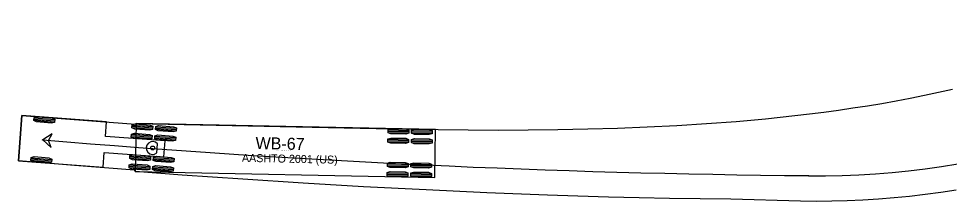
# Model space of a CAD drawing. Extents: x 1639988 to 1641860, y 841974 to 844187.
# Drawn here: x 1640630.6 to 1640795.3, y 842661.9 to 842694.2 of the extents above; entities that cross this region are included whole.
import ezdxf

# ---------------------------------------------------------------- set-up
doc = ezdxf.new("R2010")
doc.units = 0
doc.layers.add('Scratch_Level_1', color=7, linetype='Continuous')

msp = doc.modelspace()

# ---------------------------------------------------------------- linework, layer by layer
at = {"layer": 'Scratch_Level_1'}
for p, q in [((1640631.18, 842677.08), (1640630.59, 842669.1)), ((1640646.14, 842675.98), (1640631.18, 842677.08)), ((1640633.29, 842676.25), (1640636.95, 842675.95)), ((1640633.31, 842676.48), (1640636.97, 842676.17)), ((1640633.33, 842676.71), (1640636.98, 842676.4)), ((1640645.95, 842673.42), (1640646.14, 842675.98)), ((1640651.41, 842675.68), (1640651.24, 842667.19)), ((1640704.4, 842674.61), (1640651.41, 842675.68)), ((1640650.66, 842674.96), (1640654.32, 842674.7)), ((1640650.68, 842675.19), (1640654.33, 842674.93)), ((1640650.69, 842675.42), (1640654.35, 842675.15)), ((1640654.81, 842674.66), (1640658.47, 842674.39)), ((1640654.83, 842674.89), (1640658.49, 842674.62)), ((1640654.85, 842675.12), (1640658.5, 842674.85)), ((1640695.97, 842674.33), (1640699.64, 842674.25)), ((1640695.97, 842674.1), (1640699.64, 842674.02)), ((1640695.98, 842674.56), (1640699.65, 842674.48)), ((1640700.14, 842674.24), (1640703.81, 842674.17)), ((1640700.14, 842674.01), (1640703.8, 842673.94)), ((1640700.15, 842674.47), (1640703.81, 842674.4)), ((1640704.23, 842666.12), (1640704.4, 842674.61)), ((1640656.51, 842672.65), (1640645.95, 842673.42)), ((1640650.54, 842673.32), (1640654.2, 842673.05)), ((1640650.56, 842673.55), (1640654.21, 842673.28)), ((1640650.57, 842673.78), (1640654.23, 842673.51)), ((1640654.69, 842673.01), (1640658.35, 842672.75)), ((1640654.71, 842673.24), (1640658.37, 842672.98)), ((1640654.73, 842673.47), (1640658.38, 842673.2)), ((1640656.3, 842669.79), (1640656.51, 842672.65)), ((1640695.94, 842672.68), (1640699.61, 842672.6)), ((1640695.94, 842672.45), (1640699.6, 842672.37)), ((1640695.95, 842672.91), (1640699.61, 842672.83)), ((1640700.1, 842672.36), (1640703.77, 842672.29)), ((1640700.11, 842672.82), (1640703.78, 842672.75)), ((1640700.11, 842672.59), (1640703.77, 842672.52)), ((1640645.55, 842668), (1640645.74, 842670.56)), ((1640645.74, 842670.56), (1640656.3, 842669.79)), ((1640655.07, 842670.51), (1640655.19, 842672.12)), ((1640630.59, 842669.1), (1640645.55, 842668)), ((1640630.59, 842669.1), (1640630.59, 842669.1)), ((1640632.77, 842669.19), (1640636.42, 842668.88)), ((1640632.79, 842669.42), (1640636.44, 842669.11)), ((1640632.8, 842669.65), (1640636.46, 842669.34)), ((1640650.26, 842669.55), (1640653.92, 842669.28)), ((1640650.28, 842669.77), (1640653.94, 842669.51)), ((1640650.3, 842670), (1640653.95, 842669.74)), ((1640654.42, 842669.24), (1640658.08, 842668.97)), ((1640654.44, 842669.47), (1640658.09, 842669.2)), ((1640654.45, 842669.7), (1640658.11, 842669.43)), ((1640650.14, 842667.9), (1640653.8, 842667.63)), ((1640650.16, 842668.13), (1640653.82, 842667.86)), ((1640650.18, 842668.36), (1640653.83, 842668.09)), ((1640654.3, 842667.6), (1640657.96, 842667.33)), ((1640654.31, 842667.82), (1640657.97, 842667.56)), ((1640654.33, 842668.05), (1640657.99, 842667.79)), ((1640695.85, 842668.17), (1640699.52, 842668.09)), ((1640695.86, 842668.62), (1640699.53, 842668.55)), ((1640695.86, 842668.39), (1640699.52, 842668.32)), ((1640700.02, 842668.31), (1640703.69, 842668.24)), ((1640700.02, 842668.08), (1640703.68, 842668.01)), ((1640700.03, 842668.54), (1640703.69, 842668.47)), ((1640651.24, 842667.19), (1640704.23, 842666.12)), ((1640651.24, 842667.19), (1640651.24, 842667.19)), ((1640695.82, 842666.74), (1640699.49, 842666.67)), ((1640695.82, 842666.52), (1640699.48, 842666.44)), ((1640695.83, 842666.97), (1640699.49, 842666.9)), ((1640699.98, 842666.43), (1640703.65, 842666.36)), ((1640699.99, 842666.89), (1640703.66, 842666.82)), ((1640699.99, 842666.66), (1640703.65, 842666.59))]:
    msp.add_line(p, q, dxfattribs=at)
for points in [[(1640796.53, 842663.91), (1640793.78, 842663.49), (1640791.04, 842663.12), (1640788.29, 842662.81), (1640785.53, 842662.54), (1640782.78, 842662.32), (1640780.02, 842662.15), (1640777.26, 842662.03), (1640774.51, 842661.95), (1640771.75, 842661.93), (1640769, 842661.96), (1640756.66, 842662.32), (1640751.23, 842662.35), (1640745.8, 842662.43), (1640740.39, 842662.53), (1640734.98, 842662.67), (1640729.59, 842662.83), (1640724.2, 842663.02), (1640713.44, 842663.45), (1640702.71, 842663.95), (1640691.66, 842664.52), (1640680.97, 842665.15), (1640670.27, 842665.83), (1640659.55, 842666.57), (1640651.24, 842667.19), (1640651.12, 842667.44), (1640640.51, 842668.27), (1640630.59, 842669.1), (1640631.18, 842677.08), (1640651.26, 842675.59), (1640651.41, 842675.68), (1640693.88, 842674.83), (1640704.87, 842674.62), (1640710.16, 842674.56), (1640715.46, 842674.54), (1640720.75, 842674.56), (1640726.03, 842674.62), (1640731.31, 842674.72), (1640736.59, 842674.88), (1640741.85, 842675.08), (1640747.1, 842675.35), (1640752.34, 842675.67), (1640757.57, 842676.07), (1640762.78, 842676.53), (1640765.37, 842676.8), (1640767.96, 842677.08), (1640770.55, 842677.38), (1640773.13, 842677.71), (1640775.69, 842678.06), (1640778.25, 842678.43), (1640780.81, 842678.83), (1640783.35, 842679.25), (1640785.88, 842679.7), (1640788.4, 842680.18), (1640790.9, 842680.68), (1640793.39, 842681.22), (1640795.87, 842681.78)], [(1640634.88, 842672.8), (1640636.35, 842671.45), (1640635.87, 842672.71), (1640636.56, 842673.88), (1640634.88, 842672.8)]]:
    msp.add_lwpolyline(points, dxfattribs=at)
for points in [[(1640633.29, 842676.2), (1640633.34, 842676.77), (1640633.86, 842676.89), (1640636.49, 842676.67), (1640636.99, 842676.46), (1640636.94, 842675.89), (1640636.42, 842675.76), (1640633.78, 842675.98)], [(1640650.65, 842674.91), (1640650.7, 842675.48), (1640651.22, 842675.61), (1640653.85, 842675.42), (1640654.35, 842675.21), (1640654.31, 842674.64), (1640653.79, 842674.51), (1640651.15, 842674.7)], [(1640634.88, 842672.8), (1640636.35, 842671.45), (1640635.87, 842672.71), (1640636.56, 842673.88)], [(1640650.53, 842673.26), (1640650.58, 842673.83), (1640651.1, 842673.97), (1640653.73, 842673.77), (1640654.23, 842673.56), (1640654.19, 842672.99), (1640653.67, 842672.86), (1640651.03, 842673.05)], [(1640654.81, 842674.6), (1640654.85, 842675.17), (1640655.38, 842675.31), (1640658.01, 842675.12), (1640658.51, 842674.91), (1640658.47, 842674.34), (1640657.94, 842674.2), (1640655.31, 842674.39)], [(1640695.97, 842674.04), (1640695.98, 842674.61), (1640696.5, 842674.77), (1640699.14, 842674.72), (1640699.65, 842674.54), (1640699.64, 842673.97), (1640699.12, 842673.8), (1640696.48, 842673.86)], [(1640700.13, 842673.96), (1640700.15, 842674.53), (1640700.66, 842674.69), (1640703.3, 842674.64), (1640703.81, 842674.45), (1640703.8, 842673.88), (1640703.28, 842673.72), (1640700.64, 842673.77)], [(1640654.69, 842672.96), (1640654.73, 842673.53), (1640655.26, 842673.66), (1640657.89, 842673.47), (1640658.39, 842673.26), (1640658.35, 842672.69), (1640657.82, 842672.56), (1640655.19, 842672.75)], [(1640695.94, 842672.39), (1640695.95, 842672.96), (1640696.46, 842673.12), (1640699.1, 842673.07), (1640699.61, 842672.89), (1640699.6, 842672.32), (1640699.09, 842672.16), (1640696.45, 842672.21)], [(1640700.1, 842672.31), (1640700.11, 842672.88), (1640700.63, 842673.04), (1640703.27, 842672.99), (1640703.78, 842672.8), (1640703.77, 842672.23), (1640703.25, 842672.07), (1640700.61, 842672.12)], [(1640632.76, 842669.13), (1640632.81, 842669.7), (1640633.34, 842669.83), (1640635.97, 842669.61), (1640636.46, 842669.4), (1640636.42, 842668.83), (1640635.89, 842668.7), (1640633.26, 842668.92)], [(1640650.26, 842669.49), (1640650.3, 842670.06), (1640650.82, 842670.19), (1640653.46, 842670), (1640653.96, 842669.79), (1640653.92, 842669.22), (1640653.39, 842669.09), (1640650.76, 842669.28)], [(1640654.41, 842669.18), (1640654.46, 842669.76), (1640654.98, 842669.89), (1640657.61, 842669.7), (1640658.11, 842669.49), (1640658.07, 842668.92), (1640657.55, 842668.78), (1640654.91, 842668.98)], [(1640650.14, 842667.84), (1640650.18, 842668.41), (1640650.7, 842668.55), (1640653.34, 842668.36), (1640653.84, 842668.15), (1640653.8, 842667.58), (1640653.27, 842667.44), (1640650.64, 842667.63)], [(1640654.29, 842667.54), (1640654.34, 842668.11), (1640654.86, 842668.24), (1640657.49, 842668.05), (1640657.99, 842667.84), (1640657.95, 842667.27), (1640657.43, 842667.14), (1640654.79, 842667.33)], [(1640695.85, 842668.11), (1640695.86, 842668.68), (1640696.38, 842668.84), (1640699.02, 842668.79), (1640699.53, 842668.61), (1640699.52, 842668.03), (1640699, 842667.87), (1640696.36, 842667.93)], [(1640700.02, 842668.02), (1640700.03, 842668.6), (1640700.54, 842668.76), (1640703.18, 842668.7), (1640703.69, 842668.52), (1640703.68, 842667.95), (1640703.16, 842667.79), (1640700.52, 842667.84)], [(1640695.82, 842666.46), (1640695.83, 842667.03), (1640696.34, 842667.19), (1640698.98, 842667.14), (1640699.49, 842666.96), (1640699.48, 842666.38), (1640698.97, 842666.22), (1640696.33, 842666.28)], [(1640699.98, 842666.37), (1640699.99, 842666.95), (1640700.51, 842667.11), (1640703.15, 842667.06), (1640703.66, 842666.87), (1640703.65, 842666.3), (1640703.13, 842666.14), (1640700.49, 842666.19)]]:
    msp.add_lwpolyline(points, close=True, dxfattribs=at)
for centre, radius in [((1640634.88, 842672.8), 0.0417), ((1640654.32, 842671.37), 0.34), ((1640770.4, 842666.47), 0.0417), ((1640770.4, 842666.47), 0.0417)]:
    msp.add_circle(centre, radius, dxfattribs=at)
for centre, radius, start, end in [((1640771.83, 842816.46), 150, 269.456, 305.4186), ((1640787.74, 844492.39), 1826, 265.19782, 269.45598), ((1640654.32, 842671.37), 1.14, 40.822, 310.822)]:
    msp.add_arc(centre, radius, start, end, dxfattribs=at)

# ---------------------------------------------------------------- texts
for s, height, p in [('WB-67', 2.125, (1640672.51, 842671.18)), ('(c) 2019 Transoft Solutions, Inc. All rights reserved.', 0.085, (1640676.09, 842670.89)), ('AASHTO 2001 (US)', 1.4167, (1640670.11, 842668.92))]:
    msp.add_text(s, height=height, rotation=358.8437, dxfattribs=at).set_placement(p)

doc.saveas('drawing.dxf')
